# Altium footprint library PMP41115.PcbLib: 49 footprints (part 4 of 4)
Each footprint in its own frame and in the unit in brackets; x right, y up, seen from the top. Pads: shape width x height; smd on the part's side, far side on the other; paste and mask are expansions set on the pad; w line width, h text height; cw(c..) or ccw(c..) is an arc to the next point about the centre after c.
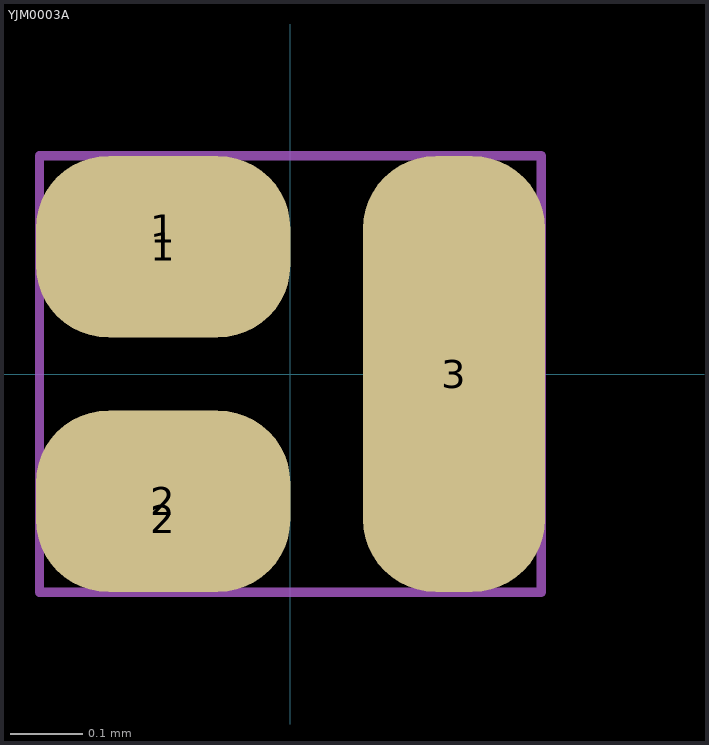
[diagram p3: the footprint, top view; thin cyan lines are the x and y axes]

## YJM0003A [mm] "SMT, 3-Leads, Body 0.69x0.6mm"
height 0.35
pads (5):
  rrect80% 0.35x0.25 smd paste-0.2 mask-0.05: 1(-0.175,0.175) 2(-0.175,-0.175)
  rrect50% 0.25x0.2 on Top Paste: 1(-0.175,0.2) 2(-0.175,-0.2)
  rrect80% 0.25x0.6 smd paste-0.05 mask-0.05: 3(0.225,0)
Mechanical 5:
  circle w0.013: c-0.25,0.2 r0.05
  lines w0.013: -0.345,-0.3 -0.345,0.3 0.345,0.3 0.345,-0.3 -0.345,-0.3
  text ".Designator" at -0.2,-0.025 h0.1
3D body "YJM0003A.stp": height 0.35, standoff 0, extent -0.345,-0.3 0.345,0.3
